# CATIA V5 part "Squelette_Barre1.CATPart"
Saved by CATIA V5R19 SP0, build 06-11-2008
Part number: Squelette_Barre1
Bounding box of the stored display mesh (mm): x -40 to 40, y -40 to 40, z 0 to 0
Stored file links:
  F:\IAO\Catia\Squelette_Barre1.CATPart
  F:\IAO\Catia\Etau.CATProduct
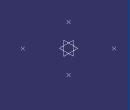
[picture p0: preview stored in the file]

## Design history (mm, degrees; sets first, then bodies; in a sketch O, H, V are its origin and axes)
External parameters (linked from other documents)
  External.Demi_longueur = 40 mm
Body1 (main body)
  Point1: (40 {= External.Demi_longueur}, 40 {= External.Demi_longueur}, 0)
  Point2: (40 {= External.Demi_longueur}, -40 {= -External.Demi_longueur}, 0)
  Point3: (-40 {= -External.Demi_longueur}, 40 {= External.Demi_longueur}, 0)
  Point4: (-40 {= -External.Demi_longueur}, -40 {= -External.Demi_longueur}, 0)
